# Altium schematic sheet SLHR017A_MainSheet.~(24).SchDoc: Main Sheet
size 431 x 279 mm; Date: Not shown in title block; ApprovedBy: Not shown in title block; CheckedBy: Not shown in title block; Author: Not shown in title block; CompanyName: Not shown in title block; DrawnBy: Kirby Kruckmeyer; Engineer: Not shown in title block; Organization: Not shown in title block; Address1: Not shown in title block; Address2: Not shown in title block; Address3: Not shown in title block; Address4: Not shown in title block; DocumentNumber: 1; Revision: Use project parameter SCH_Rev; SheetNumber: 1; SheetTotal: 2; PageSetup: Record=PageOptions¦CenterHorizontal=True¦CenterVertical=True¦PrintScale=1.00¦XCorrection=1.00¦YCorrection=1.00¦PrintKind=0¦BorderSize=5000000¦LeftOffset=0¦BottomOffset=0¦Orientation=2¦PaperLength=1000¦PaperWidth=1000¦Scale=100¦PaperSource=15¦PrintQuality=600¦MediaType=1¦DitherType=10¦PaperKind=Letter¦PrintScaleMode=1
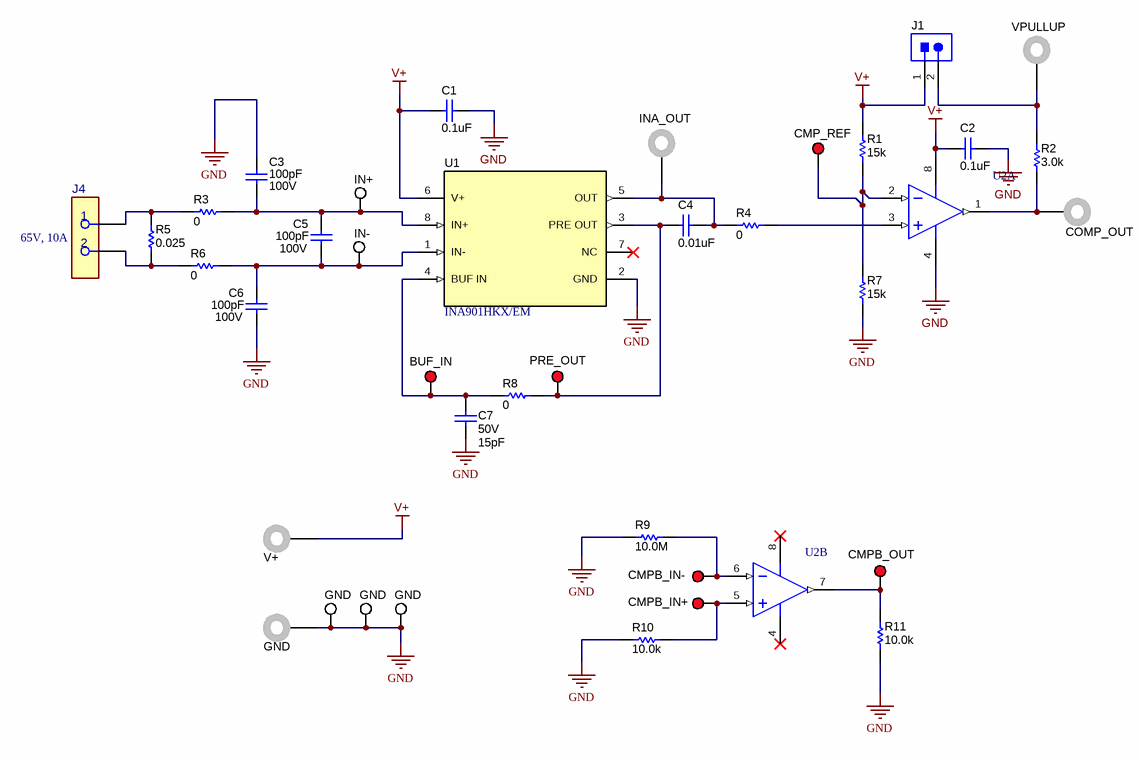
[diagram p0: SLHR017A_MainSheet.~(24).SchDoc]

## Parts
C1  ValueDisplayed: 0.1uF  [0805_HV]  (hidden comment: C0805C104K1RACTU)
C2  ValueDisplayed: 0.1uF  [0805_HV]  (hidden comment: C0805C104K1RACTU)
C3  Cap_F: 100pF  VDC_V: 100V  [0805_HV]  (hidden comment: C0805C101J1RACTU)
C4  ValueDisplayed: 0.01uF  [0805_HV]  (hidden comment: C0805C103F1GACTU)
C5  Cap_F: 100pF  VDC_V: 100V  [0805_HV]  (hidden comment: C0805C101J1RACTU)
C6  Cap_F: 100pF  VDC_V: 100V  [0805_HV]  (hidden comment: C0805C101J1RACTU)
C7  VDC_V: 50V  ValueDisplayed: 15pF  [0805_HV]  (hidden comment: VJ0805A150JXACW1BC)
J1  PBC02SAAN  [Sullins_PBC02SAAN]  (value not drawn)
J2  VPULLUP  [Keystone_575-4]
J3  INA_OUT  [Keystone_575-4]
J4  691137710002  [FP-691137710002_HDR2-MFG]  (value not drawn)
J5  COMP_OUT  [Keystone_575-4]
J6  V+  [Keystone_575-4]
J7  GND  [Keystone_575-4]
R1  ValueDisplayed: 15k  [0805_HV]  (hidden comment: ERJ-6GEYJ153V)
R2  ValueDisplayed: 3.0k  [0805_HV]  (hidden comment: ERJ-6GEYJ302V)
R3  ValueDisplayed: 0  [0805_HV]  (hidden comment: ERJ-6GEY0R00V)
R4  ValueDisplayed: 0  [0805_HV]  (hidden comment: ERJ-6GEY0R00V)
R5  ValueDisplayed: 0.025  [2512]  (hidden comment: CRA2512-FZ-R025ELF)
R6  ValueDisplayed: 0  [0805_HV]  (hidden comment: ERJ-6GEY0R00V)
R7  ValueDisplayed: 15k  [0805_HV]  (hidden comment: ERJ-6GEYJ153V)
R8  ValueDisplayed: 0  [0805_HV]  (hidden comment: ERJ-6GEY0R00V)
R9  ValueDisplayed: 10.0M  [0805_HV]  (hidden comment: CRCW080510M0FKEA)
R10  ValueDisplayed: 10.0k  [0805_HV]  (hidden comment: RNCP0805FTD10K0)
R11  ValueDisplayed: 10.0k  [0805_HV]  (hidden comment: RNCP0805FTD10K0)
TP1  CMP_REF  [Keystone5010]
TP2  IN+  [Testpoint_Keystone_Miniature]
TP3  IN-  [Testpoint_Keystone_Miniature]
TP4  BUF_IN  [Keystone5010]
TP5  PRE_OUT  [Keystone5010]
TP6  CMPB_OUT  [Keystone5010]
TP7  CMPB_IN-  [Keystone5010]
TP8  CMPB_IN+  [Keystone5010]
TP9  GND  [Testpoint_Keystone_Miniature]
TP10  GND  [Testpoint_Keystone_Miniature]
TP11  GND  [Testpoint_Keystone_Miniature]
U1  INA901HKX/EM  [HKX0008A_Custom_B]
U2  LM193AJRLQMLV  [NAB0008A]  (value not drawn)  (parts A,B of 2)

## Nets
GND: C1.2 C2.2 C3.1 C6.2 C7.2 J7.1 R7.1 R9.1 R10.1 R11.1 TP9.1 TP10.1 TP11.1 U1.2(GND) U2.4(GND)
V+: C1.1 C2.1 J1.1 J6.1 R1.2 U1.6(V+) U2.8(V+)
NetC3_2: C3.2 C5.1 R3.2 TP2.1 U1.8(IN+)
NetC4_1: C4.1 R8.2 TP5.1 U1.3(PRE_OUT)
NetC4_2: C4.2 J3.1 R4.1 U1.5(OUT)
NetC5_2: C5.2 C6.1 R6.2 TP3.1 U1.1(IN-)
NetC7_1: C7.1 R8.1 TP4.1 U1.4(BUF_IN)
NetJ1_2: J1.2 J2.1 R2.2
NetJ4_1: J4.1 R3.1 R5.2
NetJ4_2: J4.2 R5.1 R6.1
NetJ5_1: J5.1 R2.1 U2.1(OUTA)
NetR1_1: R1.1 R7.2 TP1.1 U2.2(INA-)
NetR4_2: R4.2 U2.3(INA+)
NetR9_2: R9.2 TP7.1 U2.6(INB-)
NetR10_2: R10.2 TP8.1 U2.5(INB+)
NetR11_2: R11.2 TP6.1 U2.7(OUTB)

Not connected (* = marked no-connect by the designer): U1 7(NC)*

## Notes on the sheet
- (near J4) 65V, 10A

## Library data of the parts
C1 C2 = CMP-0007722-2: CAP, CERM, 0.1 uF, 100 V, +/- 10%, X7R, 0805; Manufacturer: Kemet; TaMin_C: -55°C; ESR_ohm: 0.064; Polarized: N; SizeAreaWB_mm2: 6.75; Value1: 0.064 ohm; U/M: EA; Value: 0.1uF; TaMax_C: 125°C; SizeZ_mm: 1.45; SizeX_mm: 2; SizeY_mm: 1.25; Cap_Case: 0805; Value2: 100V; SizeArea_mm2: 2.5; Cap_F: 100nF; IRMS_A: 1.64A; AEC Category: Q200
C3 C5 C6 = CMP-0007706-2: CAP, CERM, 100 pF, 100 V, +/- 5%, X7R, 0805; Manufacturer: Kemet; TaMin_C: -55°C; Polarized: N; SizeAreaWB_mm2: 6.75; Value1: Unknown; U/M: EA; Value: 100pF; TaMax_C: 125°C; SizeZ_mm: 1.45; SizeX_mm: 2; SizeY_mm: 1.25; Cap_Case: 0805; SizeArea_mm2: 2.5; AEC Category: Q200
C4 = CMP-0007716-2: CAP, CERM, 0.01 uF, 100 V, +/- 1%, C0G/NP0, 0805; Manufacturer: Kemet; TaMin_C: -55°C; Polarized: N; SizeAreaWB_mm2: 6.75; Value1: Unknown; U/M: EA; Value: 0.01uF; TaMax_C: 125°C; SizeZ_mm: 1.45; SizeX_mm: 2; SizeY_mm: 1.25; Cap_Case: 0805; Value2: 100V; SizeArea_mm2: 2.5; Cap_F: 10nF; AEC Category: Q200
C7 = CMP-0008431-2: CAP, CERM, 15 pF, 50 V, +/- 5%, C0G/NP0, 0805; Manufacturer: Vishay-Bccomponents; TaMin_C: -55°C; Polarized: N; SizeAreaWB_mm2: 6.75; Value1: Unknown; U/M: EA; Value: 15pF; TaMax_C: 125°C; SizeZ_mm: 1.45; SizeX_mm: 2; SizeY_mm: 1.25; Cap_Case: 0805; SizeArea_mm2: 2.5; AEC Category: Q200
J1 = CMP-0054566-1: Header, 100mil, 2x1, Gold, TH; Manufacturer: Sullins Connector Solutions; CNHeader: TRUE; Current_A: 3A; Green_Lifecycle: Active; Shrouded: N; Gender: Male; Green_REACh: Passed; Voltage_V: 1.8kV; Row_Count: 1; Pitch_mm: 2.54; CT: FALSE; Cert_UL: Y
J2 J3 J5-J7 = CMP-0055165-2: Standard Banana Jack, Uninsulated, 5.5mm; Manufacturer: Keystone; PartNumber: 575-4; CT: TRUE; Green_REACh: Passed; CNHeader: FALSE; Green_Lifecycle: Active
J4 = CMP-0087503-1: TERM BLK 2POS SIDE ENTRY 5MM PCB; Manufacturer: Würth Elektronik; Symbol Name: SYM-691137710002; Row_Count: 1; Current_A: 16A; ContactFinish: Tin,Nickel; Voltage_V: 300V
R1 R7 = CMP-0020646-3: RES, 15 k, 5%, 0.125 W, AEC-Q200 Grade 0, 0805; Manufacturer: Panasonic; Power_W: 125mW; TempCo: 200 ppm/C; Value_Code: 15k0; Value: 15k; EIA_Code: E24; SizeX_mm: 2; SizeY_mm: 1.25; SizeZ_mm: 1.45; Value2: 0.125W; SizeArea_mm2: 2.5; AEC Qualified: Y; VDC_V: 150V; AEC Category: Q200; AEC Grade: 0; SizeAreaWB_mm2: 6.75
R2 = CMP-0020698-3: RES, 3.0 k, 5%, 0.125 W, AEC-Q200 Grade 0, 0805; Manufacturer: Panasonic; Power_W: 125mW; TempCo: 200 ppm/C; Value_Code: 3k00; Value: 3.0k; EIA_Code: E24; Res_ohm: 3k; SizeX_mm: 2; SizeY_mm: 1.25; SizeZ_mm: 1.45; Value2: 0.125W; SizeArea_mm2: 2.5; AEC Qualified: Y; VDC_V: 150V; AEC Category: Q200; AEC Grade: 0; SizeAreaWB_mm2: 6.75
R3 R4 R6 R8 = CMP-0020616-3: RES, 0, 5%, 0.125 W, AEC-Q200 Grade 0, 0805; Manufacturer: Panasonic; Power_W: 125mW; TempCo: 600 ppm/C; Value_Code: 0000; Value: 0; EIA_Code: E24; SizeX_mm: 2; SizeY_mm: 1.25; SizeZ_mm: 1.45; Value2: 0.125W; SizeArea_mm2: 2.5; AEC Qualified: Y; VDC_V: 150V; AEC Category: Q200; SizeAreaWB_mm2: 6.75
R5 = CMP-0015421-2: RES, 0.025, 1%, 3 W, 2512; Manufacturer: Bourns; Power_W: 3W; TempCo: 75 ppm/C; Value_Code: R025; U/M: EA; Value: 0.025; EIA_Code: E96; SizeX_mm: 6.3; SizeY_mm: 3.2; SizeZ_mm: 0.71; SizeArea_mm2: 20.16; VDC_V: 0V; AEC Category: Q200
R9 = CMP-0020846-3: RES, 10.0 M, 1%, 0.125 W, AEC-Q200 Grade 0, 0805; Manufacturer: Vishay-Dale; Power_W: 125mW; TempCo: 100 ppm/C; Value_Code: 10M0; Value: 10.0Meg; EIA_Code: E96; Res_ohm: 10M; SizeX_mm: 2; SizeY_mm: 1.25; SizeZ_mm: 1.45; Value2: 0.125W; SizeArea_mm2: 2.5; AEC Qualified: Y; VDC_V: 150V; AEC Category: Q200; AEC Grade: 0
R10 R11 = CMP-0084247-1: RES, 10.0 k, 1%, 0.25 W, AEC-Q200 Grade 0, 0805; Manufacturer: Stackpole Electronics Inc; Power_W: 250mW; Green_Lifecycle: Active; TempCo: 100 ppm/C; SizeAreaWB_mm2: 6.75; Value_Code: 10k0; Green_REACh: Passed; Value: 10.0k; EIA_Code: E96; Res_ohm: 10k; SizeX_mm: 2; SizeY_mm: 1.25; SizeZ_mm: 1.45; Value2: 0.25W; SizeArea_mm2: 2.5; AEC Qualified: Y; AEC Grade: 0; AEC Category: Q200
TP1 TP4-TP8 = CMP-0055147-1: Test Point, Multipurpose, Red, TH; Manufacturer: Keystone; PartNumber: 5010; CNHeader: FALSE; Green_Lifecycle: Active; Green_REACh: Passed; ContactFinish: Silver; CT: TRUE
TP2 TP3 TP9-TP11 = CMP-0055152-1: Test Point, Miniature, SMT; Manufacturer: Keystone; CNHeader: FALSE; Green_Lifecycle: Active; Green_REACh: Passed; CT: TRUE
U1 = CMP-0081563-2: Voltage Output, Unidirectional Measurement Current-Shunt Monitor, HKX0008A (CFP-8); Manufacturer: Texas Instruments; SizeZ_mm: 2.8; Rating: Space; AEC Category: Q200; CompType: IC; AEC Qualified: N
U2 = CMP-0067897-1: Low Power Low Offset Voltage Dual Comparator, 8-pin CerDIP; Manufacturer: Texas Instruments; High-Reliability: Y; CompType: Amplifiers; PackageTopMarking: NSZSSXXYYA*LM193AJRLV Q*5962R*9452603VPA; PowerWise: N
